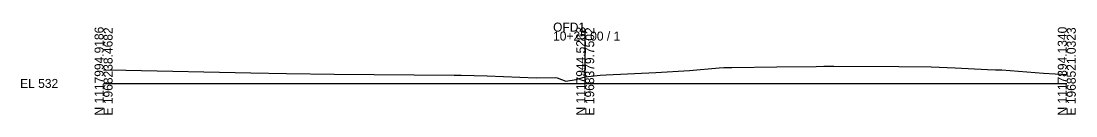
# Model space of a CAD drawing. Extents: x 9974 to 10303, y 9990 to 11518.
# Drawn here: x 9974.3 to 10302.8, y 9990.3 to 10019 of the extents above; entities that cross this region are included whole.
import ezdxf

# ---------------------------------------------------------------- set-up
doc = ezdxf.new("R2010")
doc.units = 0
for name, color, linetype in [('Level 10', 7, 'Continuous'), ('Level 60', 7, 'Continuous'), ('Level 63', 7, 'Continuous')]:
    doc.layers.add(name, color=color, linetype=linetype)

msp = doc.modelspace()

# ---------------------------------------------------------------- linework, layer by layer
at = {"layer": 'Level 60'}
for p, q in [((10000, 10004.22), (10006.88, 10004.1)), ((10006.88, 10004.1), (10045.84, 10003.28)), ((10171.99, 10003.44), (10182.48, 10004.05)), ((10182.48, 10004.05), (10191.72, 10004.83)), ((10191.72, 10004.83), (10193.22, 10004.95)), ((10193.22, 10004.95), (10195.63, 10004.97)), ((10195.63, 10004.97), (10209.64, 10005.17)), ((10209.64, 10005.17), (10221.89, 10005.32)), ((10221.89, 10005.32), (10224.36, 10005.36)), ((10224.36, 10005.36), (10227.41, 10005.39)), ((10227.41, 10005.39), (10247.7, 10005.27)), ((10247.7, 10005.27), (10257.8, 10005.21)), ((10257.8, 10005.21), (10265.21, 10004.85)), ((10265.21, 10004.85), (10275.3, 10004.4)), ((10275.3, 10004.4), (10277.77, 10004.28)), ((10277.77, 10004.28), (10279.76, 10004.2)), ((10279.76, 10004.2), (10292.79, 10003.22)), ((10045.84, 10003.28), (10056.98, 10003.11)), ((10056.98, 10003.11), (10071.85, 10002.89)), ((10071.85, 10002.89), (10109.24, 10002.6)), ((10109.24, 10002.6), (10111.34, 10002.55)), ((10111.34, 10002.55), (10119.48, 10002.37)), ((10119.48, 10002.37), (10134.71, 10001.78)), ((10134.71, 10001.78), (10140.7, 10001.81)), ((10140.7, 10001.81), (10141.23, 10001.73)), ((10141.23, 10001.73), (10144, 10000.69)), ((10144, 10000.69), (10147.23, 10001.22)), ((10147.23, 10001.22), (10150, 10002.03)), ((10150, 10002.03), (10154.71, 10002.61)), ((10154.71, 10002.61), (10156.57, 10002.65)), ((10156.57, 10002.65), (10171.99, 10003.44)), ((10292.79, 10003.22), (10300, 10002.83))]:
    msp.add_line(p, q, dxfattribs=at)
at = {"layer": 'Level 63'}
for p, q in [((10150, 10000), (10150, 10016.17)), ((10000, 10000), (10150, 10000)), ((10150, 10000), (10300, 10000))]:
    msp.add_line(p, q, dxfattribs=at)

# ---------------------------------------------------------------- texts
at = {"layer": 'Level 10'}
msp.add_text('534.035', height=0.8, rotation=90, dxfattribs=at).set_placement((10149.9, 10002.53))
at = {"layer": 'Level 63'}
for s, p in [('N 1117994.9186', (10000, 9990)), ('E 1968238.4682', (10002.8, 9990)), ('N 1117944.5263', (10150, 9990)), ('E 1968379.7502', (10152.8, 9990)), ('N 1117894.1340', (10300, 9990)), ('E 1968521.0323', (10302.8, 9990))]:
    msp.add_text(s, height=2.8, rotation=90, dxfattribs=at).set_placement(p)
for s, p in [('OFD1', (10140, 10016.17)), ('10+25.00 / 1', (10140, 10013.37)), ('EL 532', (9974, 9998.6))]:
    msp.add_text(s, height=2.8, dxfattribs=at).set_placement(p)

doc.saveas('drawing.dxf')
